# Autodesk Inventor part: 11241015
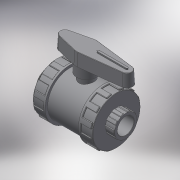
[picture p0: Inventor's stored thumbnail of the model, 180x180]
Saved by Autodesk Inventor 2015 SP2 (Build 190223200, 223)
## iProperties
Created: 2017-11
Part Number: 11241015
Material: Generic
Description: PLASSON BI STOP VALVE THR PVC 1.1/2"
Document SubType Name: Modeling
Designer: KIM
Density: 1 g/cm^3
Appearance: Default
Author: KIM
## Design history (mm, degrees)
derived "112410 - 112710.ipt"
feature "Solid1::112410 - 112710.ipt"
tag "TaggingFeature1"
body "Solid1"
other parameters: "d0" = 142, "d1" = 44.845, "d2" = 96, "d3" = 22, "d4" = 35.876, "d5" = 15.4, "d7" = 62.783, "d8" = 86.4, "d13" = 1.34535, "d23" = 22, "d24" = 92.16, "d25" = 0.8969, "d26" = 1.34535, "d27" = 14.4, "d28" = 7.2, "d29" = 16.5, "d30" = 0, "d35" = 1.34535, "d39" = 48, "d45" = 360 deg, "d47" = 0.8969, "d50" = 52.8, "d51" = 28.8, "d53" = 0, "d55" = 8.969, "d56" = 4.4845, "d57" = 15.4, "d58" = 0, "d59" = 1.34535, "d61" = 360 deg, "d63" = 38.4, "d64" = 86, "d68" = 19.2, "d69" = 33, "d70" = 21.5, "d71" = 3 deg, "d73" = 1.92, "d74" = 44, "d75" = 2.58, "d76" = 0, "d77" = 0.8969, "G_" = 44.845, "l_" = 22, "H_" = 142, "K_" = 96, "F_" = 86, "d67" = 38.4, "d72" = 9.6
